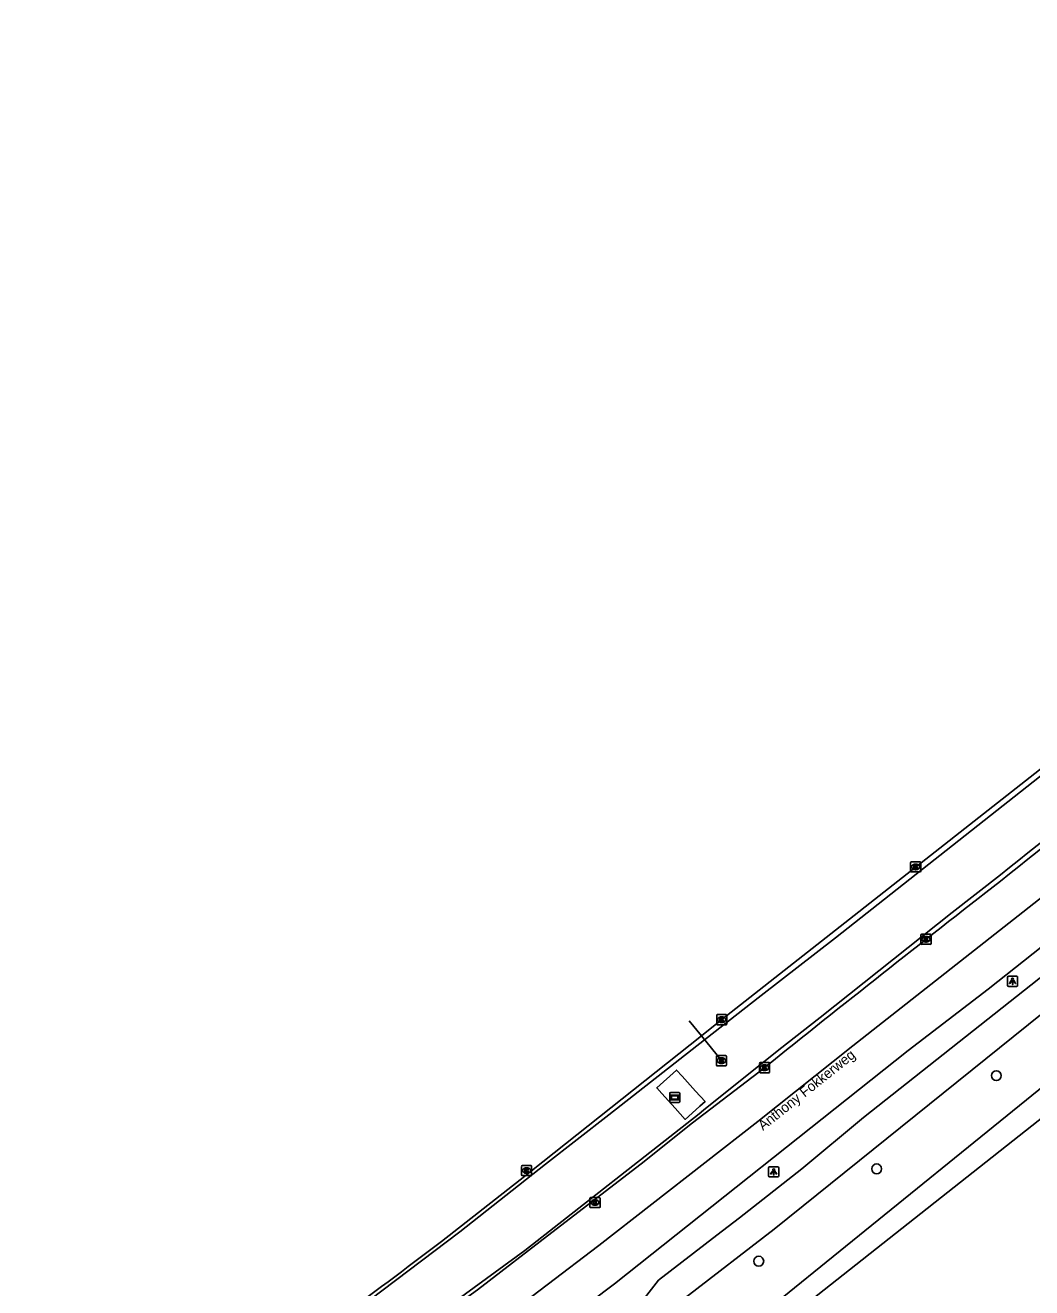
# Model space of a CAD drawing. Extents: x 157154 to 159278, y 385000 to 386650.
# Drawn here: x 157373.6 to 157473.4, y 386258 to 386383.1 of the extents above; entities that cross this region are included whole.
import ezdxf

# ---------------------------------------------------------------- set-up
doc = ezdxf.new("R2010")
doc.units = 0
for name, color, linetype in [('IMGEO_Berm_groen', 7, 'Continuous'), ('IMGEO_Berm_open', 7, 'Continuous'), ('IMGEO_Boom', 7, 'Continuous'), ('IMGEO_Duiker', 7, 'Continuous'), ('IMGEO_Fietspad_gesloten', 7, 'Continuous'), ('IMGEO_Kolk', 7, 'Continuous'), ('IMGEO_Lichtpunt', 7, 'Continuous'), ('IMGEO_Openbare_ruimte_label', 7, 'Continuous'), ('IMGEO_Reclamebord', 7, 'Continuous'), ('IMGEO_Rijbaan_regionaal_gesloten', 7, 'Continuous'), ('IMGEO_Rioolput', 7, 'Continuous'), ('IMGEO_Waterloop', 7, 'Continuous')]:
    doc.layers.add(name, color=color, linetype=linetype)

msp = doc.modelspace()

# ---------------------------------------------------------------- linework, layer by layer
at = {"layer": 'IMGEO_Berm_groen'}
msp.add_lwpolyline([(157438.76, 386278.96), (157440.09, 386277.48), (157441.02, 386276.45), (157440.5, 386275.98), (157440.1, 386275.62), (157439.06, 386274.68), (157438.06, 386275.79), (157436.75, 386277.24), (157436.24, 386277.81), (157438.2, 386279.58), (157438.76, 386278.96)], dxfattribs=at)
at = {"layer": 'IMGEO_Berm_open'}
for points in [[(157406.53, 386255.85), (157416.72, 386263.55), (157425.2, 386270.24), (157431.49, 386275.14), (157440.97, 386282.58), (157446.58, 386286.98), (157453.95, 386292.68), (157474.18, 386308.64), (157484.89, 386317.1), (157488.4, 386319.87), (157500, 386328.31), (157504.51, 386331.46), (157512.41, 386336.92), (157528.8, 386347.2), (157541.08, 386354.3), (157542.41, 386355.13), (157543.78, 386355.89), (157551.54, 386360.02), (157561.71, 386365.34), (157567.37, 386368.14), (157579.93, 386374.13), (157586.15, 386376.91), (157591.05, 386378.99), (157600.92, 386383.14)], [(157470.31, 386298.92), (157465.54, 386295.18), (157452.43, 386284.78), (157448.35, 386281.57), (157440.88, 386275.59), (157440.43, 386275.24), (157423.17, 386261.68), (157412.24, 386253.73), (157409.61, 386251.73)]]:
    msp.add_lwpolyline(points, dxfattribs=at)
msp.add_arc((157825.2, 385858.16), 565.88, 125.0775, 128.84, dxfattribs=at)
at = {"layer": 'IMGEO_Boom'}
for centre in [(157469.91, 386279.02), (157458.04, 386269.78), (157446.35, 386260.63)]:
    msp.add_circle(centre, 0.489, dxfattribs=at)
at = {"layer": 'IMGEO_Duiker'}
msp.add_lwpolyline([(157442.65, 386280.51), (157440.66, 386282.97), (157439.46, 386284.44)], dxfattribs=at)
at = {"layer": 'IMGEO_Fietspad_gesloten'}
for points in [[(157517.71, 386317.46), (157500, 386304.86), (157489.83, 386297.27), (157480.03, 386289.67), (157447.87, 386263.8), (157439.05, 386257), (157439.25, 386254.48)], [(157422.92, 386244.79), (157426.33, 386247.81), (157428.51, 386249.87), (157435.01, 386256.97), (157436.41, 386258.75), (157442.19, 386263.2), (157444.45, 386264.94), (157450.61, 386269.8), (157456.75, 386274.86), (157487.88, 386299.49), (157500, 386308.62)]]:
    msp.add_lwpolyline(points, dxfattribs=at)
at = {"layer": 'IMGEO_Kolk'}
for p, q in [((157461.41, 386299.28), (157461.41, 386300.14)), ((157461.48, 386300.21), (157462.33, 386300.21)), ((157461.9, 386299.99), (157461.92, 386299.99)), ((157462.41, 386300.14), (157462.41, 386299.28)), ((157462.33, 386299.21), (157461.48, 386299.21)), ((157461.92, 386299.43), (157461.89, 386299.43)), ((157462.43, 386292.11), (157462.43, 386292.97)), ((157462.5, 386293.04), (157463.36, 386293.04)), ((157462.92, 386292.82), (157462.94, 386292.82)), ((157463.43, 386292.97), (157463.43, 386292.11)), ((157463.36, 386292.04), (157462.5, 386292.04)), ((157462.94, 386292.26), (157462.92, 386292.26)), ((157442.18, 386284.14), (157442.18, 386284.99)), ((157442.26, 386285.07), (157443.11, 386285.07)), ((157443.18, 386284.99), (157443.18, 386284.14)), ((157443.11, 386284.07), (157442.26, 386284.07)), ((157442.67, 386284.85), (157442.69, 386284.85)), ((157442.69, 386284.29), (157442.67, 386284.29)), ((157446.42, 386279.39), (157446.42, 386280.24)), ((157446.5, 386280.31), (157447.35, 386280.31)), ((157446.91, 386280.09), (157446.94, 386280.09)), ((157447.42, 386280.24), (157447.42, 386279.39)), ((157447.35, 386279.31), (157446.5, 386279.31)), ((157446.93, 386279.53), (157446.91, 386279.53)), ((157422.83, 386269.18), (157422.83, 386270.03)), ((157422.9, 386270.11), (157423.76, 386270.11)), ((157423.83, 386270.03), (157423.83, 386269.18)), ((157423.76, 386269.11), (157422.9, 386269.11)), ((157423.34, 386269.33), (157423.31, 386269.33)), ((157423.32, 386269.89), (157423.34, 386269.89)), ((157429.61, 386266.02), (157429.61, 386266.87)), ((157429.69, 386266.95), (157430.54, 386266.95)), ((157430.1, 386266.73), (157430.13, 386266.73)), ((157430.12, 386266.17), (157430.1, 386266.17)), ((157430.61, 386266.87), (157430.61, 386266.02)), ((157430.54, 386265.95), (157429.69, 386265.95))]:
    msp.add_line(p, q, dxfattribs=at)
for points in [[(157461.41, 386299.28), (157461.41, 386300.14)], [(157461.48, 386300.21), (157462.33, 386300.21)], [(157462.41, 386300.14), (157462.41, 386299.28)], [(157462.33, 386299.21), (157461.48, 386299.21)], [(157461.73, 386299.91), (157461.85, 386299.91), (157461.85, 386299.76), (157461.98, 386299.91), (157462.15, 386299.91), (157462, 386299.76), (157462.15, 386299.51), (157462, 386299.51), (157461.92, 386299.68), (157461.85, 386299.61), (157461.85, 386299.51), (157461.73, 386299.51), (157461.73, 386299.91)], [(157462.43, 386292.11), (157462.43, 386292.97)], [(157462.5, 386293.04), (157463.36, 386293.04)], [(157462.75, 386292.74), (157462.87, 386292.74), (157462.87, 386292.59), (157463, 386292.74), (157463.17, 386292.74), (157463.02, 386292.59), (157463.17, 386292.34), (157463.02, 386292.34), (157462.94, 386292.5), (157462.87, 386292.44), (157462.87, 386292.34), (157462.75, 386292.34), (157462.75, 386292.74)], [(157463.43, 386292.97), (157463.43, 386292.11)], [(157463.36, 386292.04), (157462.5, 386292.04)], [(157442.18, 386284.14), (157442.18, 386284.99)], [(157442.26, 386285.07), (157443.11, 386285.07)], [(157443.18, 386284.99), (157443.18, 386284.14)], [(157443.11, 386284.07), (157442.26, 386284.07)], [(157442.5, 386284.77), (157442.63, 386284.77), (157442.63, 386284.62), (157442.75, 386284.77), (157442.92, 386284.77), (157442.77, 386284.62), (157442.93, 386284.37), (157442.77, 386284.37), (157442.69, 386284.53), (157442.63, 386284.47), (157442.63, 386284.37), (157442.5, 386284.37), (157442.5, 386284.77)], [(157446.42, 386279.39), (157446.42, 386280.24)], [(157446.5, 386280.31), (157447.35, 386280.31)], [(157446.74, 386280.01), (157446.87, 386280.01), (157446.87, 386279.86), (157447, 386280.01), (157447.16, 386280.01), (157447.01, 386279.86), (157447.17, 386279.61), (157447.01, 386279.61), (157446.93, 386279.78), (157446.87, 386279.71), (157446.87, 386279.61), (157446.74, 386279.61), (157446.74, 386280.01)], [(157447.42, 386280.24), (157447.42, 386279.39)], [(157447.35, 386279.31), (157446.5, 386279.31)], [(157422.83, 386269.18), (157422.83, 386270.03)], [(157422.9, 386270.11), (157423.76, 386270.11)], [(157423.83, 386270.03), (157423.83, 386269.18)], [(157423.76, 386269.11), (157422.9, 386269.11)], [(157423.15, 386269.81), (157423.27, 386269.81), (157423.27, 386269.65), (157423.4, 386269.81), (157423.57, 386269.81), (157423.42, 386269.66), (157423.57, 386269.41), (157423.42, 386269.41), (157423.34, 386269.57), (157423.27, 386269.5), (157423.27, 386269.41), (157423.15, 386269.41), (157423.15, 386269.81)], [(157429.61, 386266.02), (157429.61, 386266.87)], [(157429.69, 386266.95), (157430.54, 386266.95)], [(157429.93, 386266.65), (157430.06, 386266.65), (157430.06, 386266.49), (157430.19, 386266.65), (157430.35, 386266.65), (157430.2, 386266.5), (157430.36, 386266.25), (157430.2, 386266.25), (157430.12, 386266.41), (157430.06, 386266.34), (157430.06, 386266.25), (157429.93, 386266.25), (157429.93, 386266.65)], [(157430.61, 386266.87), (157430.61, 386266.02)], [(157430.54, 386265.95), (157429.69, 386265.95)]]:
    msp.add_lwpolyline(points, dxfattribs=at)
for centre, start, end in [((157461.48, 386300.14), 91.552, 178.448), ((157461.48, 386300.14), 91.552, 178.448), ((157462.33, 386300.14), 1.552, 88.448), ((157462.33, 386300.14), 1.552, 88.448), ((157461.48, 386299.29), 181.552, 268.448), ((157461.48, 386299.29), 181.552, 268.448), ((157462.33, 386299.29), 271.552, 358.448), ((157462.33, 386299.29), 271.552, 358.448), ((157462.51, 386292.96), 91.552, 178.448), ((157462.51, 386292.96), 91.552, 178.448), ((157463.35, 386292.96), 1.552, 88.448), ((157463.35, 386292.96), 1.552, 88.448), ((157462.51, 386292.11), 181.552, 268.448), ((157462.51, 386292.11), 181.552, 268.448), ((157463.35, 386292.11), 271.552, 358.448), ((157463.35, 386292.11), 271.552, 358.448), ((157442.26, 386284.99), 91.552, 178.448), ((157442.26, 386284.99), 91.552, 178.448), ((157443.11, 386284.99), 1.552, 88.448), ((157443.11, 386284.99), 1.552, 88.448), ((157442.26, 386284.14), 181.552, 268.448), ((157442.26, 386284.14), 181.552, 268.448), ((157443.11, 386284.14), 271.552, 358.448), ((157443.11, 386284.14), 271.552, 358.448), ((157446.5, 386280.24), 91.552, 178.448), ((157446.5, 386280.24), 91.552, 178.448), ((157447.35, 386280.24), 1.552, 88.448), ((157447.35, 386280.24), 1.552, 88.448), ((157446.5, 386279.39), 181.552, 268.448), ((157446.5, 386279.39), 181.552, 268.448), ((157447.35, 386279.39), 271.552, 358.448), ((157447.35, 386279.39), 271.552, 358.448), ((157422.91, 386270.03), 91.552, 178.448), ((157422.91, 386270.03), 91.552, 178.448), ((157423.75, 386270.03), 1.552, 88.448), ((157423.75, 386270.03), 1.552, 88.448), ((157422.91, 386269.18), 181.552, 268.448), ((157422.91, 386269.18), 181.552, 268.448), ((157423.75, 386269.18), 271.552, 358.448), ((157423.75, 386269.18), 271.552, 358.448), ((157429.69, 386266.87), 91.552, 178.448), ((157429.69, 386266.87), 91.552, 178.448), ((157430.54, 386266.87), 1.552, 88.448), ((157430.54, 386266.87), 1.552, 88.448), ((157429.69, 386266.02), 181.552, 268.448), ((157429.69, 386266.02), 181.552, 268.448), ((157430.54, 386266.02), 271.552, 358.448), ((157430.54, 386266.02), 271.552, 358.448)]:
    msp.add_arc(centre, 0.0765, start, end, dxfattribs=at)
for centre, major_axis, ratio, start_param, end_param in [((157461.89, 386299.71), (-0.387, 0.002), 0.722429, 4.712389, 7.853982), ((157461.92, 386299.71), (-0.39, 0.002), 0.717154, 1.570796, 4.712389), ((157462.92, 386292.54), (-0.387, 0.002), 0.722429, 4.712389, 7.853982), ((157462.94, 386292.54), (-0.39, 0.002), 0.717154, 1.570796, 4.712389), ((157442.67, 386284.57), (-0.387, 0.002), 0.722429, 4.712389, 7.853982), ((157442.69, 386284.57), (-0.39, 0.002), 0.717154, 1.570796, 4.712389), ((157446.91, 386279.81), (-0.387, 0.002), 0.722429, 4.712389, 7.853982), ((157446.93, 386279.81), (-0.39, 0.002), 0.717154, 1.570796, 4.712389), ((157423.32, 386269.61), (-0.387, 0.002), 0.722429, 4.712389, 7.853982), ((157423.34, 386269.61), (-0.39, 0.002), 0.717154, 1.570796, 4.712389), ((157430.1, 386266.45), (-0.387, 0.002), 0.722429, 4.712389, 7.853982), ((157430.12, 386266.45), (-0.39, 0.002), 0.717154, 1.570796, 4.712389)]:
    msp.add_ellipse(centre, major_axis=major_axis, ratio=ratio, start_param=start_param, end_param=end_param, dxfattribs=at)
at = {"layer": 'IMGEO_Lichtpunt'}
for p, q in [((157471.01, 386288.77), (157471.01, 386287.97)), ((157471.01, 386288.77), (157471.01, 386287.97)), ((157471.92, 386288.87), (157471.11, 386288.87)), ((157471.92, 386288.87), (157471.11, 386288.87)), ((157472.01, 386287.97), (157472.01, 386288.77)), ((157472.01, 386287.97), (157472.01, 386288.77)), ((157471.11, 386287.87), (157471.92, 386287.87)), ((157471.11, 386287.87), (157471.92, 386287.87)), ((157448.23, 386269.98), (157447.42, 386269.98)), ((157448.23, 386269.98), (157447.42, 386269.98)), ((157447.33, 386269.89), (157447.33, 386269.08)), ((157447.33, 386269.89), (157447.33, 386269.08)), ((157447.42, 386268.98), (157448.23, 386268.98)), ((157447.42, 386268.98), (157448.23, 386268.98)), ((157448.33, 386269.08), (157448.33, 386269.89)), ((157448.33, 386269.08), (157448.33, 386269.89))]:
    msp.add_line(p, q, dxfattribs=at)
for points in [[(157471.39, 386288.44), (157471.43, 386288.41), (157471.24, 386288.15), (157471.2, 386288.17), (157471.39, 386288.44)], [(157471.49, 386288.39), (157471.54, 386288.39), (157471.54, 386288.07), (157471.49, 386288.07), (157471.49, 386288.39)], [(157471.6, 386288.41), (157471.64, 386288.44), (157471.82, 386288.17), (157471.79, 386288.15), (157471.6, 386288.41)], [(157447.7, 386269.55), (157447.74, 386269.52), (157447.55, 386269.26), (157447.52, 386269.29), (157447.7, 386269.55)], [(157447.8, 386269.5), (157447.85, 386269.5), (157447.85, 386269.18), (157447.8, 386269.18), (157447.8, 386269.5)], [(157447.91, 386269.52), (157447.95, 386269.55), (157448.14, 386269.29), (157448.1, 386269.26), (157447.91, 386269.52)]]:
    msp.add_lwpolyline(points, dxfattribs=at)
for centre in [(157471.51, 386288.57), (157447.83, 386269.68)]:
    msp.add_circle(centre, 0.0994, dxfattribs=at)
for centre, start, end in [((157471.11, 386288.77), 90, 180), ((157471.11, 386288.77), 90, 180), ((157471.92, 386288.77), 0, 90), ((157471.92, 386288.77), 0, 90), ((157471.11, 386287.97), 180, 270), ((157471.11, 386287.97), 180, 270), ((157471.92, 386287.97), 270, 0), ((157471.92, 386287.97), 270, 360), ((157447.42, 386269.89), 90, 180), ((157447.42, 386269.89), 90, 180), ((157448.23, 386269.89), 0, 90), ((157448.23, 386269.89), 0, 90), ((157447.42, 386269.08), 180, 270), ((157447.42, 386269.08), 180, 270), ((157448.23, 386269.08), 270, 0), ((157448.23, 386269.08), 270, 360)]:
    msp.add_arc(centre, 0.0946, start, end, dxfattribs=at)
at = {"layer": 'IMGEO_Reclamebord'}
for p, q in [((157437.52, 386276.46), (157437.52, 386277.26)), ((157437.52, 386277.26), (157437.52, 386276.46)), ((157437.62, 386277.36), (157438.41, 386277.36)), ((157438.41, 386277.36), (157437.62, 386277.36)), ((157438.41, 386276.36), (157437.62, 386276.36)), ((157437.62, 386276.36), (157438.41, 386276.36)), ((157438.51, 386277.26), (157438.51, 386276.46)), ((157438.51, 386276.46), (157438.51, 386277.26))]:
    msp.add_line(p, q, dxfattribs=at)
for points in [[(157437.62, 386277.09), (157438.41, 386277.09), (157438.41, 386276.63), (157437.62, 386276.63), (157437.62, 386277.09)], [(157437.69, 386277.03), (157437.69, 386276.69), (157438.34, 386276.69), (157438.34, 386277.03), (157437.69, 386277.03)]]:
    msp.add_lwpolyline(points, dxfattribs=at)
for centre, start, end in [((157437.62, 386277.26), 90, 180), ((157437.62, 386277.26), 90, 180), ((157437.62, 386276.46), 180, 270), ((157437.62, 386276.46), 180, 270), ((157438.41, 386277.26), 0, 90), ((157438.41, 386277.26), 360, 90), ((157438.41, 386276.46), 270, 0), ((157438.41, 386276.46), 270, 0)]:
    msp.add_arc(centre, 0.1, start, end, dxfattribs=at)
at = {"layer": 'IMGEO_Rijbaan_regionaal_gesloten'}
for points in [[(157601.75, 386372.59), (157587.17, 386366.22), (157572.76, 386359.43), (157562.16, 386354.16), (157548.16, 386346.64), (157537.84, 386340.64), (157523.61, 386331.94), (157513.51, 386325.31), (157499.63, 386315.57), (157486.75, 386306.11), (157474.53, 386296.81), (157455.69, 386281.96), (157446.25, 386274.48), (157430.5, 386262.2), (157420.26, 386254.38), (157411.04, 386247.62), (157399.37, 386239.35), (157382.38, 386227.42), (157373.63, 386221.32)], [(157424.69, 386252.83), (157432.05, 386258.39), (157461.17, 386281.5), (157469.09, 386287.6), (157477.06, 386293.91), (157480.29, 386296.49), (157492.62, 386305.95), (157505.08, 386314.92), (157516.2, 386322.45), (157519.95, 386325.04), (157532.17, 386332.79), (157542.75, 386339.22), (157556.23, 386346.76), (157568.35, 386353.16), (157586.87, 386361.94), (157598.41, 386367.06)], [(157414.88, 386262.59), (157422.7, 386268.68), (157440.66, 386282.97), (157442.68, 386284.57), (157488.4, 386320.5)], [(157383.65, 386233.28), (157385.33, 386234.37), (157389.31, 386237.13), (157407.86, 386250), (157411.47, 386252.75), (157418.46, 386257.79), (157425.84, 386263.47), (157434.7, 386270.29), (157439.77, 386274.36), (157446.92, 386279.81)]]:
    msp.add_lwpolyline(points, dxfattribs=at)
for centre, radius, start, end in [((157825.2, 385857.55), 565.88, 125.0775, 128.84), ((158559.36, 384896.8), 1774.89, 127.84901, 128.81164), ((157139.93, 386620.32), 451.19, 304.1883, 307.5465)]:
    msp.add_arc(centre, radius, start, end, dxfattribs=at)
at = {"layer": 'IMGEO_Rioolput'}
for p, q in [((157442.15, 386280.08), (157442.15, 386280.93)), ((157442.23, 386281.01), (157443.08, 386281.01)), ((157443.08, 386280.01), (157442.23, 386280.01)), ((157442.64, 386280.79), (157442.67, 386280.79)), ((157442.66, 386280.23), (157442.64, 386280.23)), ((157443.16, 386280.93), (157443.16, 386280.08))]:
    msp.add_line(p, q, dxfattribs=at)
for points in [[(157442.15, 386280.08), (157442.15, 386280.93)], [(157442.23, 386281.01), (157443.08, 386281.01)], [(157443.08, 386280.01), (157442.23, 386280.01)], [(157442.74, 386280.71), (157442.49, 386280.71), (157442.49, 386280.31)], [(157442.49, 386280.31), (157442.62, 386280.31), (157442.62, 386280.47), (157442.63, 386280.47)], [(157442.67, 386280.63), (157442.62, 386280.63), (157442.62, 386280.55)], [(157442.62, 386280.55), (157442.67, 386280.55)], [(157442.67, 386280.44), (157442.74, 386280.31), (157442.88, 386280.31), (157442.82, 386280.43)], [(157443.16, 386280.93), (157443.16, 386280.08)]]:
    msp.add_lwpolyline(points, dxfattribs=at)
for centre, radius, start, end in [((157442.23, 386280.93), 0.0765, 91.552, 178.448), ((157442.23, 386280.93), 0.0765, 91.552, 178.448), ((157442.23, 386280.08), 0.0765, 181.552, 268.448), ((157442.23, 386280.08), 0.0765, 181.552, 268.448), ((157442.62, 386280.42), 0.0533, 26.0293, 88.6989), ((157442.67, 386280.53), 0.0964, 77.0061, 93.1865), ((157442.65, 386280.74), 0.19, 274.7715, 282.9687), ((157442.69, 386280.59), 0.0378, 276.6634, 79.6772), ((157442.74, 386280.6), 0.109, 350.3612, 89.416), ((157442.74, 386280.6), 0.112, 277.5842, 350.9817), ((157442.72, 386280.38), 0.108, 29.5134, 73.7905), ((157443.08, 386280.93), 0.0765, 1.552, 88.448), ((157443.08, 386280.93), 0.0765, 1.552, 88.448), ((157443.08, 386280.08), 0.0765, 271.552, 358.448), ((157443.08, 386280.08), 0.0765, 271.552, 358.448)]:
    msp.add_arc(centre, radius, start, end, dxfattribs=at)
for centre, major_axis, ratio, start_param, end_param in [((157442.64, 386280.51), (-0.387, 0.002), 0.722429, 4.712389, 7.853982), ((157442.67, 386280.51), (-0.39, 0.002), 0.717154, 1.570796, 4.712389)]:
    msp.add_ellipse(centre, major_axis=major_axis, ratio=ratio, start_param=start_param, end_param=end_param, dxfattribs=at)
at = {"layer": 'IMGEO_Waterloop'}
for points in [[(157446.02, 386252.41), (157445.55, 386253.01), (157444.84, 386253.9), (157483, 386284.82), (157500, 386297.74), (157524.03, 386314.84)], [(157447.02, 386253.2), (157479.88, 386279.13), (157500, 386294.54), (157508.79, 386301.27), (157517.75, 386307.77)]]:
    msp.add_lwpolyline(points, dxfattribs=at)

# ---------------------------------------------------------------- texts
at = {"layer": 'IMGEO_Openbare_ruimte_label'}
msp.add_text('Anthony Fokkerweg', height=1, rotation=38.5435, dxfattribs=at).set_placement((157446.77, 386273.54))

doc.saveas('drawing.dxf')
